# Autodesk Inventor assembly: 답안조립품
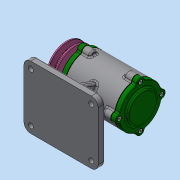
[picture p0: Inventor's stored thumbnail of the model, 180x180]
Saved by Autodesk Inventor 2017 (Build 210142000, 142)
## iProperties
Part Number: 답안조립품
Material: 일반
Document SubType Name: Assembly
Designer: MRC
Author: MRC
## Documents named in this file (12)
- C:\Users\MRC\Desktop\720716V1008\답안조립품.iam
- C:\Users\MRC\Desktop\720716V1008\본체.ipt
- C:\Users\MRC\Desktop\720716V1008\V-벨트풀리.ipt
- C:\Users\MRC\Desktop\720716V1008\너트 M12 x 1.25.ipt
- C:\Users\MRC\Desktop\720716V1008\뒤커버.ipt
- C:\Users\MRC\Desktop\720716V1008\앞커버.ipt
- C:\Users\MRC\Desktop\720716V1008\오일 실.ipt
- C:\Users\MRC\Desktop\720716V1008\축.ipt
- C:\Users\MRC\Desktop\720716V1008\키 4 x 4.ipt
- C:\Users\MRC\Desktop\720716V1008\개스킷.ipt
- C:\Users\MRC\Desktop\720716V1008\베어링 6204.ipt
- C:\Users\MRC\Desktop\720716V1008\볼트 M4 x 12.ipt
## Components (3 placed, 2 different names)
1. V-벨트풀리:1
2. 개스킷:1
3. 개스킷:2
